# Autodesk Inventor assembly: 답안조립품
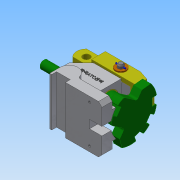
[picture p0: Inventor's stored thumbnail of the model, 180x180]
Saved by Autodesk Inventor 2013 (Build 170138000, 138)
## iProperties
Created: 2016-11
Part Number: 답안조립품
Document SubType Name: Assembly
Designer: Administrator
Author: Administrator
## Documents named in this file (8)
- C:\Users\Administrator\Desktop\461108V1039\답안조립품.iam
- C:\Users\Administrator\Desktop\461108V1039\본체.ipt
- C:\Users\Administrator\Desktop\461108V1039\부시.ipt
- C:\Users\Administrator\Desktop\461108V1039\분할대.ipt
- C:\Users\Administrator\Desktop\461108V1039\분할축.ipt
- C:\Users\Administrator\Desktop\461108V1039\와셔.ipt
- C:\Users\Administrator\Desktop\461108V1039\원통형핀.ipt
- C:\Users\Administrator\Desktop\461108V1039\클레비스핀.ipt
